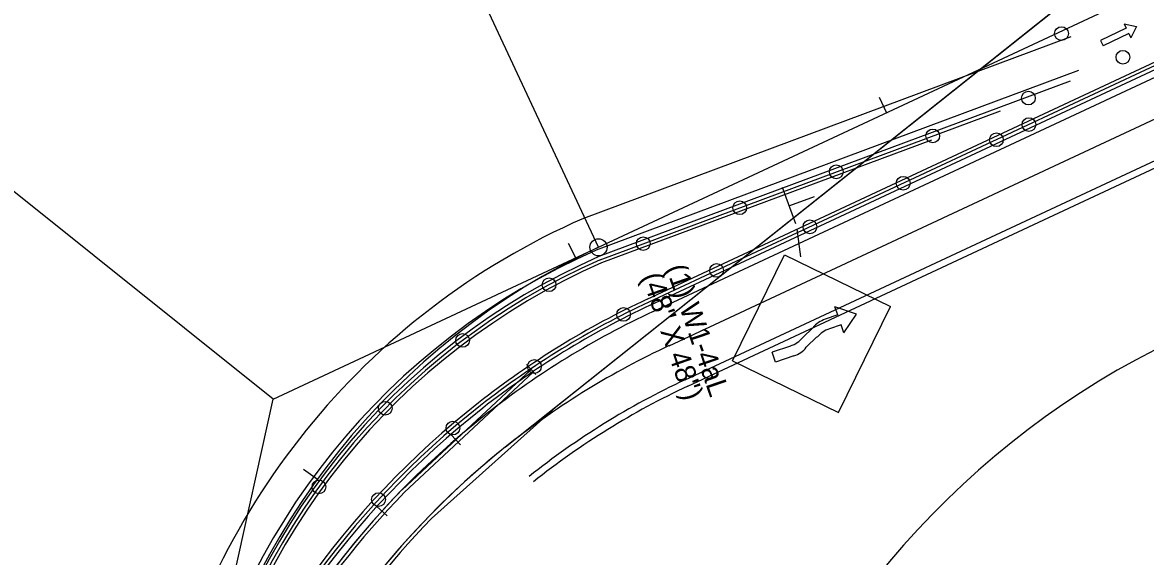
# Model space of a CAD drawing. Extents: x 659657 to 668193, y 633084 to 648639.
# Drawn here: x 661493.6 to 661820.9, y 642657.6 to 642813.2 of the extents above; entities that cross this region are included whole.
import ezdxf

# ---------------------------------------------------------------- set-up
doc = ezdxf.new("R2010")
doc.units = 0
for name, color, linetype in [('R_Border PE', 7, 'Continuous'), ('R_MOT_Stage 1', 7, 'Continuous'), ('R_MOT_Stage 1_Striping', 7, 'Continuous'), ('R_MOT_Stage 2', 7, 'Continuous'), ('R_MOT_Stage 2_Striping', 7, 'Continuous'), ('R_MOT_Stage 3', 7, 'Continuous'), ('R_MOT_Stage 3_Striping', 7, 'Continuous'), ('R_MOT_Stage 3_Striping_PPM', 7, 'Continuous'), ('R_MOT_Stage 4_Striping_PPM', 7, 'Continuous'), ('R_MOT_Stage 5_Striping_PPM', 7, 'Continuous'), ('S_EXISTING_ALIGNMENT', 7, 'Continuous'), ('T_SIGNAL CONTROL CABINET', 7, 'Continuous')]:
    doc.layers.add(name, color=color, linetype=linetype)

msp = doc.modelspace()

# ---------------------------------------------------------------- linework, layer by layer
at = {"layer": 'R_Border PE'}
for p, q in [((661718.97, 642754.51), (661715.09, 642765.07)), ((661717.2, 642759.82), (661724.41, 642762.46)), ((661720.42, 642744.94), (661719.37, 642752.99)), ((661700.57, 642714.63), (661715.7, 642745.49)), ((661715.7, 642745.49), (661746.57, 642730.38)), ((661731.21, 642727.95), (661730.39, 642730.33)), ((661736.65, 642728.21), (661730.39, 642730.33)), ((661731.45, 642699.51), (661746.57, 642730.38)), ((661731.21, 642727.95), (661727.58, 642726.71)), ((661733.01, 642722.71), (661736.65, 642728.21)), ((661723.98, 642724.23), (661721.05, 642721.42)), ((661732.19, 642725.09), (661728.8, 642723.93)), ((661733.01, 642722.71), (661732.19, 642725.09)), ((661725.12, 642721.54), (661722.02, 642718.56)), ((661717.45, 642718.91), (661712.07, 642717.07)), ((661713.05, 642714.21), (661712.07, 642717.07)), ((661718.43, 642716.06), (661713.05, 642714.21)), ((661700.57, 642714.63), (661731.45, 642699.51))]:
    msp.add_line(p, q, dxfattribs=at)
for centre, start, end in [((661729.85, 642719.53), 107.5759, 141.3338), ((661731.07, 642716.76), 107.5759, 141.3338), ((661715.17, 642726.12), 287.5759, 321.3338), ((661716.16, 642723.23), 287.5759, 321.3338)]:
    msp.add_arc(centre, 7.52, start, end, dxfattribs=at)
at = {"layer": 'R_MOT_Stage 1'}
for p, q in [((661798.98, 642796.14), (661661.59, 642744.99)), ((661758.54, 642778.95), (661662.34, 642743.13))]:
    msp.add_line(p, q, dxfattribs=at)
for centre in [(661814.33, 642803.06), (661786.78, 642791.17), (661758.88, 642780.14), (661730.76, 642769.67), (661702.65, 642759.21), (661674.53, 642748.74), (661647.08, 642736.75), (661621.88, 642720.53), (661599.35, 642700.75), (661580.01, 642677.85)]:
    msp.add_circle(centre, 2, dxfattribs=at)
for radius, start in [(202.63, 113.7798), (200.63, 113.7965)]:
    msp.add_arc((661743.29, 642559.56), radius, start, 168.4903, dxfattribs=at)
at = {"layer": 'R_MOT_Stage 1_Striping'}
for p, q in [((661661.48, 642747.69), (661849.86, 642835.69)), ((661799.18, 642809.02), (661657.08, 642756.11)), ((661801.41, 642799.18), (661660.84, 642746.84)), ((661566.65, 642703.4), (661661.48, 642747.69)), ((661544.08, 642601.2), (661566.65, 642703.4))]:
    msp.add_line(p, q, dxfattribs=at)
for points in [[(661661.48, 642747.69), (661576.83, 642928.9)], [(661566.65, 642703.4), (661410.59, 642828.47)], [(661743.31, 642791.44), (661745.43, 642786.91)], [(661652.61, 642748.92), (661654.88, 642744.47)], [(661575.52, 642683.03), (661579.57, 642680.09)]]:
    msp.add_lwpolyline(points, dxfattribs=at)
msp.add_circle((661661.48, 642747.69), 2.5, dxfattribs=at)
for centre, radius, start, end in [((661743.29, 642559.56), 214.63, 113.6846, 168.4903), ((661743.29, 642559.56), 204.63, 113.7633, 168.4903), ((661751.29, 642555.43), 212.21, 115.0389, 167.5452)]:
    msp.add_arc(centre, radius, start, end, dxfattribs=at)
at = {"layer": 'R_MOT_Stage 2'}
for p, q in [((661675.7, 642732.61), (661863.92, 642820.53)), ((661676.54, 642730.79), (661864.76, 642818.72)), ((661687.55, 642707.24), (661875.77, 642795.16))]:
    msp.add_line(p, q, dxfattribs=at)
for centre in [(661796.42, 642809.97), (661786.94, 642783.46), (661777.45, 642779.03), (661750.27, 642766.34), (661723.09, 642753.64), (661695.91, 642740.94), (661668.78, 642728.13), (661642.8, 642712.94), (661619.07, 642695), (661597.37, 642674.14)]:
    msp.add_circle(centre, 2, dxfattribs=at)
for radius, start, end in [(253.73, 115.0389, 128.1046), (251.73, 115.0389, 128.1017), (225.73, 115.0389, 128.5196), (253.73, 128.1046, 161.5452), (251.73, 128.1017, 161.5452)]:
    msp.add_arc((661783.09, 642502.72), radius, start, end, dxfattribs=at)
at = {"layer": 'R_MOT_Stage 2_Striping'}
for p, q in [((661661.48, 642747.69), (661849.86, 642835.69)), ((661677.39, 642728.98), (661865.61, 642816.9)), ((661682.05, 642719.01), (661870.27, 642806.94)), ((661686.7, 642709.05), (661874.92, 642796.97)), ((661566.65, 642703.4), (661661.48, 642747.69)), ((661544.08, 642601.2), (661566.65, 642703.4))]:
    msp.add_line(p, q, dxfattribs=at)
for points in [[(661661.48, 642747.69), (661576.83, 642928.9)], [(661566.65, 642703.4), (661410.59, 642828.47)], [(661743.31, 642791.44), (661745.43, 642786.91)], [(661652.61, 642748.92), (661654.88, 642744.47)], [(661575.52, 642683.03), (661579.57, 642680.09)]]:
    msp.add_lwpolyline(points, dxfattribs=at)
msp.add_circle((661661.48, 642747.69), 2.5, dxfattribs=at)
for centre, radius, start, end in [((661751.29, 642555.43), 212.21, 115.0389, 167.5452), ((661783.09, 642502.72), 249.73, 115.0389, 128.1075), ((661783.09, 642502.72), 238.73, 115.0389, 128.1051), ((661783.09, 642502.72), 227.73, 115.0389, 128.5196), ((661783.09, 642502.72), 249.73, 128.1075, 161.5452), ((661783.09, 642502.72), 238.73, 128.1051, 161.5452)]:
    msp.add_arc(centre, radius, start, end, dxfattribs=at)
at = {"layer": 'R_MOT_Stage 3'}
for p, q in [((661640.5, 642713.51), (661643.23, 642710.58)), ((661641.82, 642712.02), (661639.82, 642710.16)), ((661618.55, 642693.06), (661621.28, 642690.14)), ((661619.87, 642691.57), (661617.87, 642689.71)), ((661598.31, 642670.72), (661596.48, 642668.7)), ((661596.88, 642672.1), (661599.84, 642669.41))]:
    msp.add_line(p, q, dxfattribs=at)
at = {"layer": 'R_MOT_Stage 3_Striping'}
for p, q in [((661642.47, 642711.26), (661604.91, 642676.27)), ((661649.94, 642701.87), (661612.79, 642668.6))]:
    msp.add_line(p, q, dxfattribs=at)
for radius in [248.73, 237.73]:
    msp.add_arc((661783.09, 642502.72), radius, 135.7536, 161.5452, dxfattribs=at)
at = {"layer": 'R_MOT_Stage 3_Striping_PPM'}
msp.add_line((661649.94, 642701.87), (661997.42, 642978.46), dxfattribs=at)
at = {"layer": 'R_MOT_Stage 4_Striping_PPM'}
for p, q in [((661649.93, 642701.88), (661997.41, 642978.47)), ((661634.41, 642689.5), (661649.94, 642701.87))]:
    msp.add_line(p, q, dxfattribs=at)
for centre, radius, start, end in [((660777.38, 642087.58), 954.93, 348.72774, 348.72774), ((661783.09, 642502.72), 238.73, 128.5196, 161.5452)]:
    msp.add_arc(centre, radius, start, end, dxfattribs=at)
at = {"layer": 'R_MOT_Stage 5_Striping_PPM'}
msp.add_line((661634.41, 642689.5), (661997.42, 642978.46), dxfattribs=at)
for centre, radius, start, end in [((660777.38, 642087.58), 954.93, 348.72774, 348.72774), ((661783.09, 642502.72), 238.73, 128.5196, 161.5452)]:
    msp.add_arc(centre, radius, start, end, dxfattribs=at)
at = {"layer": 'S_EXISTING_ALIGNMENT'}
msp.add_arc((661937.25, 642496.11), 249.11, 115.6664, 161.5452, dxfattribs=at)
at = {"layer": 'T_SIGNAL CONTROL CABINET'}
for p, q in [((661864.34, 642819.62), (661676.12, 642731.7)), ((661815.28, 642811.52), (661807.81, 642807.97)), ((661814.68, 642812.79), (661815.28, 642811.52)), ((661814.68, 642812.79), (661818.28, 642812.01)), ((661818.28, 642812.01), (661816.61, 642808.72)), ((661807.81, 642807.97), (661808.53, 642806.44)), ((661816.01, 642809.99), (661808.53, 642806.44)), ((661816.01, 642809.99), (661816.61, 642808.72)), ((661661.97, 642744.06), (661778.61, 642787.49)), ((661641.82, 642712.02), (661604.23, 642677))]:
    msp.add_line(p, q, dxfattribs=at)
for centre, radius, start, end in [((661743.29, 642559.56), 201.63, 113.7881, 168.4903), ((661783.09, 642502.72), 252.73, 115.0389, 128.1046), ((661783.09, 642502.72), 252.73, 128.1046, 161.5452), ((661783.09, 642502.72), 249.73, 135.7536, 161.5452)]:
    msp.add_arc(centre, radius, start, end, dxfattribs=at)

# ---------------------------------------------------------------- texts
at = {"layer": 'R_Border PE'}
for s, p in [('(1) W1-4aL', (661681.09, 642741.62)), ('(48" X 48")', (661673.99, 642739.19))]:
    msp.add_text(s, height=6, rotation=288.9009, dxfattribs=at).set_placement(p)

doc.saveas('drawing.dxf')
